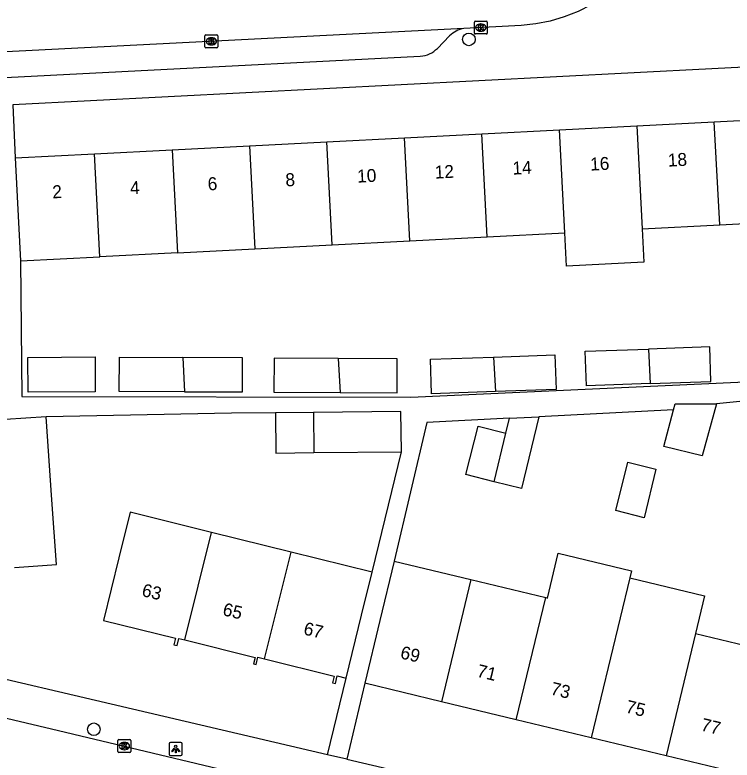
# Model space of a CAD drawing. Extents: x 161084 to 161928, y 385355 to 386522.
# Drawn here: x 161364 to 161419.4, y 385855.9 to 385913.5 of the extents above; entities that cross this region are included whole.
import ezdxf

# ---------------------------------------------------------------- set-up
doc = ezdxf.new("R2010")
doc.units = 0
for name, color, linetype in [('IMGEO_Boom', 7, 'Continuous'), ('IMGEO_Kolk', 7, 'Continuous'), ('IMGEO_Lichtpunt', 7, 'Continuous'), ('IMGEO_Pand', 7, 'Continuous'), ('IMGEO_Pand_nummerreeks', 7, 'Continuous'), ('IMGEO_Rijbaan_lokaal_open', 7, 'Continuous'), ('IMGEO_Voetpad_open', 7, 'Continuous')]:
    doc.layers.add(name, color=color, linetype=linetype)

msp = doc.modelspace()

# ---------------------------------------------------------------- linework, layer by layer
at = {"layer": 'IMGEO_Boom'}
for centre in [(161399.08, 385911.626), (161370.075, 385858.266)]:
    msp.add_circle(centre, 0.489, dxfattribs=at)
at = {"layer": 'IMGEO_Kolk'}
for p, q in [((161399.506, 385912.119), (161399.506, 385912.971)), ((161399.581, 385913.045), (161400.433, 385913.045)), ((161399.994, 385912.825), (161400.019, 385912.825)), ((161400.507, 385912.971), (161400.507, 385912.119)), ((161400.433, 385912.045), (161399.581, 385912.045)), ((161400.017, 385912.265), (161399.992, 385912.265)), ((161378.671, 385911.049), (161378.671, 385911.901)), ((161378.746, 385911.975), (161379.598, 385911.975)), ((161379.159, 385911.755), (161379.184, 385911.755)), ((161379.672, 385911.901), (161379.672, 385911.049)), ((161379.598, 385910.975), (161378.746, 385910.975)), ((161379.182, 385911.195), (161379.157, 385911.195)), ((161371.939, 385856.544), (161371.939, 385857.396)), ((161372.014, 385857.47), (161372.866, 385857.47)), ((161372.427, 385857.25), (161372.452, 385857.25)), ((161372.94, 385857.396), (161372.94, 385856.544)), ((161372.45, 385856.69), (161372.425, 385856.69)), ((161372.866, 385856.47), (161372.014, 385856.47))]:
    msp.add_line(p, q, dxfattribs=at)
for points in [[(161399.506, 385912.119), (161399.506, 385912.971)], [(161399.581, 385913.045), (161400.433, 385913.045)], [(161399.827, 385912.745), (161399.95, 385912.745), (161399.95, 385912.594), (161400.08, 385912.745), (161400.244, 385912.745), (161400.098, 385912.594), (161400.251, 385912.345), (161400.099, 385912.345), (161400.014, 385912.509), (161399.95, 385912.442), (161399.95, 385912.345), (161399.827, 385912.345), (161399.827, 385912.745)], [(161400.507, 385912.971), (161400.507, 385912.119)], [(161400.433, 385912.045), (161399.581, 385912.045)], [(161378.671, 385911.049), (161378.671, 385911.901)], [(161378.746, 385911.975), (161379.598, 385911.975)], [(161378.992, 385911.675), (161379.115, 385911.675), (161379.115, 385911.524), (161379.245, 385911.675), (161379.409, 385911.675), (161379.263, 385911.524), (161379.416, 385911.275), (161379.264, 385911.275), (161379.179, 385911.439), (161379.115, 385911.372), (161379.115, 385911.275), (161378.992, 385911.275), (161378.992, 385911.675)], [(161379.672, 385911.901), (161379.672, 385911.049)], [(161379.598, 385910.975), (161378.746, 385910.975)], [(161371.939, 385856.544), (161371.939, 385857.396)], [(161372.014, 385857.47), (161372.866, 385857.47)], [(161372.94, 385857.396), (161372.94, 385856.544)], [(161372.26, 385857.17), (161372.383, 385857.17), (161372.383, 385857.019), (161372.513, 385857.17), (161372.677, 385857.17), (161372.531, 385857.019), (161372.684, 385856.77), (161372.532, 385856.77), (161372.447, 385856.934), (161372.383, 385856.867), (161372.383, 385856.77), (161372.26, 385856.77), (161372.26, 385857.17)], [(161372.866, 385856.47), (161372.014, 385856.47)]]:
    msp.add_lwpolyline(points, dxfattribs=at)
for centre, start, end in [((161399.583, 385912.969), 91.55205, 178.44795), ((161399.583, 385912.969), 91.55205, 178.44795), ((161400.431, 385912.969), 1.55205, 88.44795), ((161400.431, 385912.969), 1.55205, 88.44795), ((161399.583, 385912.121), 181.55205, 268.44795), ((161399.583, 385912.121), 181.55205, 268.44795), ((161400.431, 385912.121), 271.55205, 358.44795), ((161400.431, 385912.121), 271.55205, 358.44795), ((161378.748, 385911.899), 91.55205, 178.44795), ((161378.748, 385911.899), 91.55205, 178.44795), ((161379.596, 385911.899), 1.55205, 88.44795), ((161379.596, 385911.899), 1.55205, 88.44795), ((161378.748, 385911.051), 181.55205, 268.44795), ((161378.748, 385911.051), 181.55205, 268.44795), ((161379.596, 385911.051), 271.55205, 358.44795), ((161379.596, 385911.051), 271.55205, 358.44795), ((161372.016, 385857.394), 91.55205, 178.44795), ((161372.016, 385857.394), 91.55205, 178.44795), ((161372.864, 385857.394), 1.55205, 88.44795), ((161372.864, 385857.394), 1.55205, 88.44795), ((161372.016, 385856.546), 181.55205, 268.44795), ((161372.016, 385856.546), 181.55205, 268.44795), ((161372.864, 385856.546), 271.55205, 358.44795), ((161372.864, 385856.546), 271.55205, 358.44795)]:
    msp.add_arc(centre, 0.0765, start, end, dxfattribs=at)
for centre, major_axis, ratio, start_param, end_param in [((161399.993, 385912.545), (-0.387, 0.002), 0.722429, 4.712389, 7.853982), ((161400.018, 385912.545), (-0.39, 0.002), 0.717154, 1.570796, 4.712389), ((161379.158, 385911.475), (-0.387, 0.002), 0.722429, 4.712389, 7.853982), ((161379.183, 385911.475), (-0.39, 0.002), 0.717154, 1.570796, 4.712389), ((161372.426, 385856.97), (-0.387, 0.002), 0.722429, 4.712389, 7.853982), ((161372.451, 385856.97), (-0.39, 0.002), 0.717154, 1.570796, 4.712389)]:
    msp.add_ellipse(centre, major_axis=major_axis, ratio=ratio, start_param=start_param, end_param=end_param, dxfattribs=at)
at = {"layer": 'IMGEO_Lichtpunt'}
for p, q in [((161376.811, 385857.245), (161376.003, 385857.245)), ((161376.811, 385857.245), (161376.003, 385857.245)), ((161375.909, 385857.15), (161375.909, 385856.343)), ((161375.909, 385857.15), (161375.909, 385856.343)), ((161376.905, 385856.343), (161376.905, 385857.15)), ((161376.905, 385856.343), (161376.905, 385857.15)), ((161376.003, 385856.249), (161376.811, 385856.249)), ((161376.003, 385856.249), (161376.811, 385856.249))]:
    msp.add_line(p, q, dxfattribs=at)
for points in [[(161376.283, 385856.814), (161376.322, 385856.786), (161376.134, 385856.524), (161376.096, 385856.551), (161376.283, 385856.814)], [(161376.385, 385856.766), (161376.432, 385856.766), (161376.432, 385856.444), (161376.385, 385856.444), (161376.385, 385856.766)], [(161376.495, 385856.786), (161376.533, 385856.813), (161376.72, 385856.551), (161376.681, 385856.523), (161376.495, 385856.786)]]:
    msp.add_lwpolyline(points, dxfattribs=at)
msp.add_circle((161376.408, 385856.948), 0.0994, dxfattribs=at)
for centre, start, end in [((161376.003, 385857.15), 90, 180), ((161376.003, 385857.15), 90, 180), ((161376.811, 385857.15), 0, 90), ((161376.811, 385857.15), 0, 90), ((161376.003, 385856.343), 180, 270), ((161376.003, 385856.343), 180, 270), ((161376.811, 385856.343), 270, 0), ((161376.811, 385856.343), 270, 360)]:
    msp.add_arc(centre, 0.0946, start, end, dxfattribs=at)
at = {"layer": 'IMGEO_Pand'}
for points in [[(161412.075, 385904.943), (161418.067, 385905.252)], [(161418.067, 385905.252), (161424.07, 385905.561)], [(161418.482, 385897.287), (161418.067, 385905.252)], [(161400.091, 385904.325), (161406.083, 385904.634)], [(161406.083, 385904.634), (161412.075, 385904.943)], [(161406.498, 385896.67), (161406.083, 385904.634)], [(161412.075, 385904.943), (161412.49, 385896.979)], [(161388.107, 385903.707), (161394.099, 385904.016)], [(161394.099, 385904.016), (161400.091, 385904.325)], [(161394.514, 385896.052), (161394.099, 385904.016)], [(161400.506, 385896.361), (161400.091, 385904.325)], [(161376.122, 385903.089), (161382.115, 385903.398)], [(161382.115, 385903.398), (161388.107, 385903.707)], [(161382.115, 385903.398), (161382.529, 385895.434)], [(161388.521, 385895.743), (161388.107, 385903.707)], [(161363.991, 385902.464), (161370.131, 385902.781)], [(161370.131, 385902.781), (161376.122, 385903.089)], [(161370.546, 385894.817), (161370.131, 385902.781)], [(161376.122, 385903.089), (161376.537, 385895.126)], [(161363.991, 385902.464), (161364.248, 385897.471), (161364.401, 385894.5)], [(161418.482, 385897.287), (161424.334, 385897.589)], [(161412.49, 385896.979), (161418.482, 385897.287)], [(161400.506, 385896.361), (161406.498, 385896.67)], [(161412.49, 385896.979), (161412.623, 385894.394), (161406.631, 385894.085), (161406.498, 385896.67)], [(161388.521, 385895.743), (161394.514, 385896.052)], [(161394.514, 385896.052), (161400.506, 385896.361)], [(161376.537, 385895.126), (161382.529, 385895.434)], [(161382.529, 385895.434), (161388.521, 385895.743)], [(161364.401, 385894.5), (161370.546, 385894.817)], [(161376.537, 385895.126), (161370.546, 385894.817)], [(161413.114, 385885.001), (161417.806, 385885.161), (161417.714, 385887.841), (161412.975, 385887.678)], [(161400.991, 385887.06), (161405.73, 385887.223), (161405.822, 385884.543), (161401.13, 385884.383)], [(161413.114, 385885.001), (161408.179, 385884.832), (161408.087, 385887.511), (161412.975, 385887.678)], [(161412.975, 385887.678), (161413.114, 385885.001)], [(161370.188, 385884.366), (161364.985, 385884.336), (161364.969, 385887.036), (161370.173, 385887.066), (161370.188, 385884.366)], [(161377.097, 385884.379), (161372.043, 385884.403), (161372.055, 385887.042), (161376.96, 385887.019)], [(161376.96, 385887.019), (161377.097, 385884.379)], [(161377.097, 385884.379), (161381.565, 385884.358), (161381.578, 385886.997), (161376.96, 385887.019)], [(161388.978, 385886.947), (161384.019, 385886.971), (161384.007, 385884.331), (161389.115, 385884.307)], [(161388.978, 385886.947), (161389.115, 385884.307)], [(161389.115, 385884.307), (161393.529, 385884.286), (161393.541, 385886.926), (161388.978, 385886.947)], [(161401.13, 385884.383), (161396.195, 385884.214), (161396.103, 385886.893), (161400.991, 385887.06)], [(161400.991, 385887.06), (161401.13, 385884.383)], [(161418.222, 385883.441), (161417.118, 385879.422), (161414.162, 385880.153), (161414.916, 385882.971)], [(161414.916, 385882.971), (161415.042, 385883.441), (161418.222, 385883.441)], [(161387.06, 385882.774), (161384.114, 385882.745)], [(161384.114, 385882.745), (161384.148, 385879.634), (161387.093, 385879.666)], [(161393.86, 385879.738), (161393.827, 385882.84), (161387.06, 385882.774)], [(161387.06, 385882.774), (161387.093, 385879.666)], [(161366.385, 385882.442), (161363.253, 385882.221)], [(161363.95, 385870.789), (161367.189, 385871.017), (161366.838, 385876.005), (161366.385, 385882.442)], [(161404.496, 385882.44), (161403.148, 385876.882), (161401.047, 385877.411)], [(161401.952, 385881.175), (161402.228, 385882.324)], [(161402.228, 385882.324), (161404.496, 385882.44)], [(161401.047, 385877.411), (161398.852, 385877.964), (161399.797, 385881.717), (161401.952, 385881.175)], [(161401.047, 385877.411), (161401.952, 385881.175)], [(161387.093, 385879.666), (161393.86, 385879.738)], [(161411.387, 385878.931), (161413.541, 385878.389), (161412.636, 385874.625), (161410.442, 385875.178), (161411.387, 385878.931)], [(161379.172, 385873.498), (161372.887, 385875.051), (161372.02, 385871.542), (161370.82, 385866.688), (161376.399, 385865.31), (161376.275, 385864.811), (161376.521, 385864.751), (161376.654, 385865.288), (161377.109, 385865.176)], [(161377.109, 385865.176), (161379.172, 385873.498)], [(161385.335, 385871.975), (161379.172, 385873.498)], [(161383.287, 385863.711), (161385.335, 385871.975)], [(161391.608, 385870.425), (161385.335, 385871.975)], [(161405.024, 385868.456), (161405.166, 385868.422), (161405.997, 385871.885), (161411.651, 385870.526), (161411.523, 385869.991)], [(161393.298, 385871.274), (161392.195, 385866.685), (161391.026, 385861.823)], [(161393.298, 385871.274), (161399.229, 385869.849)], [(161389.583, 385862.23), (161390.783, 385867.085), (161391.608, 385870.425)], [(161411.523, 385869.991), (161408.548, 385857.612)], [(161411.523, 385869.991), (161417.318, 385868.598), (161416.614, 385865.671)], [(161399.229, 385869.849), (161396.957, 385860.398)], [(161399.229, 385869.849), (161405.024, 385868.456)], [(161402.753, 385859.005), (161405.024, 385868.456)], [(161416.614, 385865.671), (161414.342, 385856.219)], [(161416.614, 385865.671), (161422.409, 385864.278)], [(161377.109, 385865.176), (161382.546, 385863.832), (161382.424, 385863.335), (161382.628, 385863.285), (161382.766, 385863.84), (161383.287, 385863.711)], [(161383.287, 385863.711), (161388.668, 385862.382), (161388.541, 385861.871), (161388.755, 385861.818), (161388.899, 385862.399), (161389.583, 385862.23)], [(161396.957, 385860.398), (161391.026, 385861.823)], [(161402.753, 385859.005), (161396.957, 385860.398)], [(161408.548, 385857.612), (161402.753, 385859.005)], [(161414.342, 385856.219), (161408.548, 385857.612)], [(161420.137, 385854.826), (161414.342, 385856.219)]]:
    msp.add_lwpolyline(points, dxfattribs=at)
at = {"layer": 'IMGEO_Rijbaan_lokaal_open'}
for points in [[(161411.224, 385916.273), (161410.433, 385915.569), (161409.519, 385914.886), (161408.548, 385914.288), (161407.528, 385913.779), (161406.465, 385913.364), (161405.37, 385913.044), (161404.251, 385912.824), (161403.117, 385912.705), (161398.69, 385912.468)], [(161398.69, 385912.468), (161345.55, 385909.752)], [(161469.483, 385833.788), (161447.797, 385838.953), (161443.995, 385839.867), (161441.191, 385840.536), (161366.79, 385858.283), (161357.51, 385860.468), (161341.03, 385864.349), (161340.797, 385864.409), (161340.28, 385864.577), (161339.781, 385864.791), (161339.302, 385865.048), (161338.849, 385865.348), (161338.424, 385865.686), (161338.031, 385866.061), (161337.673, 385866.47), (161337.353, 385866.909), (161337.074, 385867.375), (161336.837, 385867.864), (161336.645, 385868.372)]]:
    msp.add_lwpolyline(points, dxfattribs=at)
at = {"layer": 'IMGEO_Voetpad_open'}
for points in [[(161396.651, 385910.936), (161397.595, 385911.896)], [(161349.142, 385907.971), (161395.327, 385910.341)], [(161423.947, 385907.942), (161423.887, 385909.661), (161363.805, 385906.561)], [(161363.805, 385906.561), (161363.991, 385902.464)], [(161364.401, 385894.5), (161364.506, 385884.014), (161394.6, 385883.953), (161431.117, 385885.643), (161431.1, 385885.952)], [(161423.612, 385883.982), (161418.222, 385883.441)], [(161384.114, 385882.745), (161380.734, 385882.712), (161366.385, 385882.442)], [(161414.916, 385882.971), (161404.496, 385882.44)], [(161402.228, 385882.324), (161395.822, 385881.998), (161393.298, 385871.274)], [(161391.608, 385870.425), (161393.86, 385879.738)], [(161388.154, 385856.304), (161343.64, 385866.716)], [(161388.154, 385856.304), (161389.583, 385862.23)], [(161391.026, 385861.823), (161389.632, 385855.958)], [(161389.632, 385855.958), (161388.154, 385856.304)], [(161389.632, 385855.958), (161413.574, 385850.358), (161441.922, 385843.544), (161448.132, 385842.052)]]:
    msp.add_lwpolyline(points, dxfattribs=at)
for centre, radius, start, end in [((161398.972, 385910.595), 1.894, 98.55071, 136.61212), ((161395.226, 385912.336), 1.998, 272.8938, 315.5041)]:
    msp.add_arc(centre, radius, start, end, dxfattribs=at)

# ---------------------------------------------------------------- texts
at = {"layer": 'IMGEO_Pand_nummerreeks'}
for s, rotation, p in [('18', 2.95092, (161414.495, 385901.783)), ('14', 2.95092, (161402.477, 385901.164)), ('16', 2.95073, (161408.486, 385901.474)), ('10', 2.95092, (161390.464, 385900.544)), ('12', 2.95092, (161396.466, 385900.854)), ('8', 2.95092, (161384.917, 385900.258)), ('4', 2.95092, (161372.897, 385899.638)), ('6', 2.95092, (161378.905, 385899.948)), ('2', 2.95092, (161366.887, 385899.329)), ('63', 346.63461, (161373.726, 385868.587)), ('65', 346.63461, (161379.98, 385867.101)), ('67', 346.63461, (161386.234, 385865.615)), ('69', 346.48587, (161393.718, 385863.768)), ('71', 346.48587, (161399.64, 385862.345)), ('73', 346.48393, (161405.342, 385860.975)), ('75', 346.48393, (161411.153, 385859.578)), ('77', 346.48587, (161416.965, 385858.181))]:
    msp.add_text(s, height=1, rotation=rotation, dxfattribs=at).set_placement(p)

doc.saveas('drawing.dxf')
